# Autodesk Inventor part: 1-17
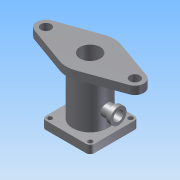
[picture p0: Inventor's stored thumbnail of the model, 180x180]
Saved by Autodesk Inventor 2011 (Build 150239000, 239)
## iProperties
Created: 2014-02
Part Number: 1-17
Document SubType Name: Modeling
Designer: Administrator
Density: 1 g/cm^3
Author: Administrator
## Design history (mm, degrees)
sketch "草图1"
  geometry: L1 (-6, 6)-(6, 6); L2 (6, 6)-(6, -6); L3 (6, -6)-(-6, -6); L4 (-6, -6)-(-6, 6); 3 further points
  constraints: 8 end point, 2 midpoint, 2 parallel, 1 horizontal, 1 horizontal alignment, 1 perpendicular, 1 vertical alignment
  dimensions: "d0" = 12 distance of L1.end L2.end; "d1" = 12 distance of L2.end L3.end
extrude "拉伸1" new body sketch "草图1" distance "d2" = 2; taper "d3" = 0 deg
fillet "圆角1" dims "d4" = 1
sketch "草图2"
  geometry: C1 r 4.319 at (0, 0); 1 further point
  constraints: 1 centre point, 1 coincident
extrude "拉伸2" join sketch "草图2" distance "d5" = 12; taper "d6" = 0 deg
sketch "草图3"
  geometry: L1 (-11.743, 2.161)-(-1.982, 5.61); L2 (11.743, 2.161)-(1.982, 5.61); L3 (-11.756, -2.041)-(-1.999, -5.553); L4 (11.756, -2.041)-(1.999, -5.553); C1 r 4.319 at (0, 0) reference; A1 r 2.231 centre (-11, 0.058) between (-11.743, 2.161) and (-11.756, -2.041); A2 r 2.231 centre (11, 0.058) between (11.756, -2.041) and (11.743, 2.161); A3 r 5.902 centre (0, 0) between (-1.999, -5.553) and (1.999, -5.553); A4 r 5.95 centre (0, 0) between (1.982, 5.61) and (-1.982, 5.61); 1 further point
  constraints: 8 end point, 8 point on circle, 8 tangent, 4 centre point, 1 coincident, 1 equal radius, 1 vertical alignment, 2 other
  dimensions: "d48" = 22 distance of A2.centre A1.centre
extrude "拉伸3" join sketch "草图3" distance "d7" = 2; taper "d8" = 0 deg
sketch "草图4"
  geometry: C1 r 1.25 at (-11, 0.058); C2 r 1.25 at (11, 0.058); A1 r 2.231 centre (-11, 0.058) between (-11.743, 2.161) and (-11.756, -2.041) reference; A2 r 2.231 centre (11, 0.058) between (11.756, -2.041) and (11.743, 2.161) reference
  constraints: 2 centre point, 2 coincident
  dimensions: "d9" = 2.5 diameter of C1; "d10" = 2.5 diameter of C2
extrude "拉伸4" cut sketch "草图4" distance "d11" = 2; taper "d12" = 0 deg
sketch "草图5"
  geometry: C1 r 0.6 at (5, 5); C2 r 0.6 at (5, -5); C3 r 0.6 at (-5, -5); C4 r 0.6 at (-5, 5); A1 r 1 centre (-5, -5) between (-6, -5) and (-5, -6) reference; A2 r 1 centre (5, -5) between (5, -6) and (6, -5) reference; A3 r 1 centre (5, 5) between (6, 5) and (5, 6) reference; A4 r 1 centre (-5, 5) between (-5, 6) and (-6, 5) reference
  constraints: 4 centre point, 4 coincident
  dimensions: "d13" = 1.2 diameter of C1; "d14" = 1.2 diameter of C2; "d15" = 1.2 diameter of C3; "d16" = 1.2 diameter of C4
extrude "拉伸5" cut sketch "草图5" stored distance "d17" = 2; taper "d18" = 0 deg
sketch "草图6"
  geometry: C1 r 4.319 at (0, 0) reference; C2 r 2.5 at (0, 0)
  constraints: 1 centre point, 1 coincident
  dimensions: "d19" = 5 diameter of C2
extrude "拉伸6" cut sketch "草图6" stored distance "d20" = 2; taper "d21" = 0 deg
node "工作平面1"
sketch "草图9"
  geometry: L1 (-2, 10)-(-2, 0) reference; C1 r 1.5 at (-5.978, 5); 2 further points
  constraints: 1 centre point, 1 horizontal alignment, 1 midpoint
  dimensions: "d28" = 3 diameter of C1
extrude "拉伸9" join sketch "草图9" stored distance "d29" = 2; taper "d30" = 0 deg
sketch "草图10"
  geometry: C1 r 1.5 at (0, 0) reference; C2 r 2 at (0, 0); 1 further point
  constraints: 1 centre point, 1 coincident
  dimensions: "d31" = 4 diameter of C2
extrude "拉伸10" join sketch "草图10" distance "d32" = 1; taper "d33" = 0 deg
sketch "草图11"
  geometry: C1 r 2 at (0, 0) reference; C2 r 1.25 at (0, 0); 1 further point
  constraints: 1 centre point, 1 coincident
  dimensions: "d34" = 2.5 diameter of C2
extrude "拉伸11" cut sketch "草图11" stored distance "d35" = 1; taper "d36" = 0 deg
sketch "草图12"
  geometry: C1 r 1.5 at (5, -9.884) reference; 1 further point
extrude "拉伸12" join sketch "草图12" stored distance "d37" = 10; taper "d38" = 0 deg
hole "Hole1" diameter "d41" = 2; stored, may be unused: countersink angle "d45" = 90 deg, drill point angle "d47" = 0 deg; dims "d39" = 10, "d40" = 10, "d42" = 6, "d43" = 4, "d44" = 2, "d46" = 8
node "实体1"
